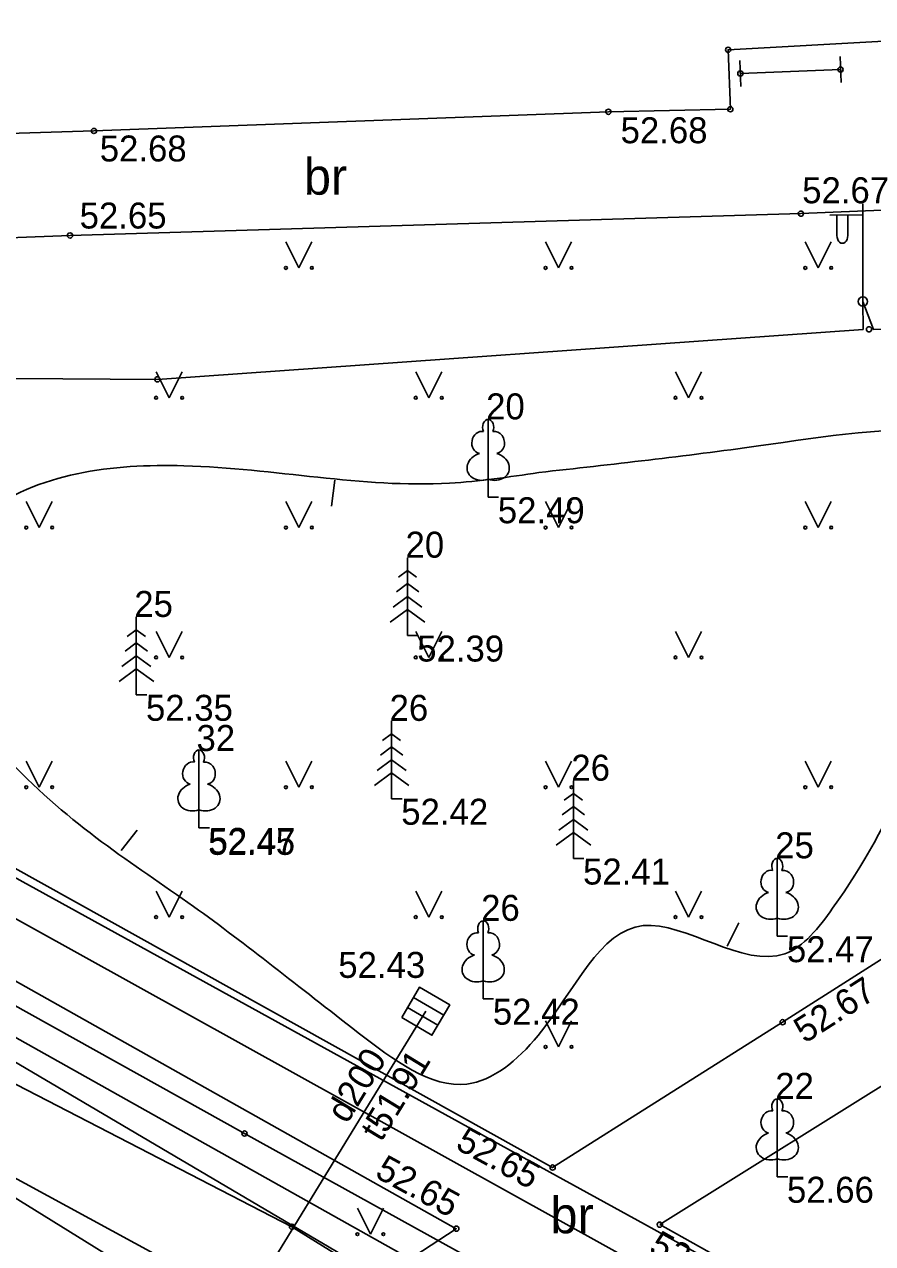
# Model space of a CAD drawing. Extents: x 619806 to 620082, y 405176 to 405386.
# Drawn here: x 619852.21 to 619868.55, y 405268.71 to 405292.19 of the extents above; entities that cross this region are included whole.
import ezdxf

# ---------------------------------------------------------------- set-up
doc = ezdxf.new("R2010")
doc.units = 0
for name, color, linetype in [('24', 7, 'Continuous'), ('APGR_SARK_####_####_#', 7, 'Continuous'), ('APGS_ELEM_####_####_#', 7, 'Continuous'), ('APGS_VADP_ZSPR_####_#', 7, 'Continuous'), ('BUVE_SOLS_####_####_#', 7, 'Continuous'), ('CELI_CMAL_####_####_#', 7, 'Continuous'), ('CELI_CSEG_####_TKST_#', 7, 'Continuous'), ('ELEK_VADP_ZSPR_####_#', 7, 'Continuous'), ('LKAN_ELEM_####_####_#', 7, 'Continuous'), ('LKAN_ELEM_PAST_TKST_#', 7, 'Continuous'), ('LKAN_VADP_PAST_####_#', 7, 'Continuous'), ('LKAN_VADP_PAST_TKST_#', 7, 'Continuous'), ('RAMI_UZMR_####_####_#', 7, 'Continuous'), ('RELJ_AATZ_####_TKST_#', 7, 'Continuous'), ('RELJ_ELEM_####_####_#', 7, 'Continuous'), ('RELJ_HORZ_PAMT_####_#', 7, 'Continuous'), ('ROBZ_UZMR_####_####_#', 7, 'Continuous'), ('SAKK_KKAN_####_####_#', 7, 'Continuous'), ('SAKT_VADP_KABE_####_#', 7, 'Continuous'), ('TERT_DIAM_####_TKST_#', 7, 'Continuous'), ('TERT_ELEM_####_####_#', 7, 'Continuous')]:
    doc.layers.add(name, color=color, linetype=linetype)

msp = doc.modelspace()

# ---------------------------------------------------------------- linework, layer by layer
at = {"layer": '24'}
msp.add_line((619862.459, 405270.018), (619864.152, 405269.086), dxfattribs=at)
at = {"layer": 'APGR_SARK_####_####_#'}
msp.add_lwpolyline([(619990.053, 405197.403), (619966.019, 405209.806), (619941.986, 405222.21), (619880.273, 405256.839), (619818.56, 405291.467)], dxfattribs=at)
at = {"layer": 'APGS_ELEM_####_####_#'}
for p, q in [((619868.359, 405286.853), (619868.359, 405288.736)), ((619868.359, 405288.52), (619867.724, 405288.515)), ((619867.859, 405288.516), (619867.859, 405288.124)), ((619868.069, 405288.518), (619868.069, 405288.124))]:
    msp.add_line(p, q, dxfattribs=at)
msp.add_circle((619868.359, 405286.853), 0.09, dxfattribs=at)
msp.add_ellipse((619867.964, 405288.124), major_axis=(0, 0.151), ratio=0.695971, start_param=1.570796, end_param=4.712389, dxfattribs=at)
at = {"layer": 'APGS_VADP_ZSPR_####_#'}
for points in [[(619889.151, 405287.633), (619888.839, 405287.188), (619868.564, 405286.313), (619868.359, 405286.853), (619868.361, 405286.315), (619854.776, 405285.354), (619845.67, 405285.418), (619844.273, 405285.984), (619845.432, 405287.623), (619843.395, 405290.297), (619835.199, 405289.5), (619828.336, 405290.779), (619827.279, 405290.766)], [(619827.279, 405290.766), (619828.233, 405290.484), (619831.689, 405284.666), (619835.137, 405280.637), (619844.802, 405275.519), (619857.367, 405269.037), (619864.044, 405264.897), (619871.373, 405258.791), (619881.17, 405253.384), (619884.232, 405252.778), (619898.622, 405244.594), (619910.805, 405239.254), (619917.273, 405236.249), (619923.426, 405231.863), (619936.8, 405224.512), (619938.618, 405223.547), (619972.929, 405204.127)]]:
    msp.add_lwpolyline(points, dxfattribs=at)
at = {"layer": 'BUVE_SOLS_####_####_#'}
for p, q in [((619867.938, 405291.069), (619867.918, 405291.569)), ((619866.009, 405290.993), (619865.989, 405291.493)), ((619865.999, 405291.243), (619867.928, 405291.319))]:
    msp.add_line(p, q, dxfattribs=at)
at = {"layer": 'CELI_CMAL_####_####_#'}
for points in [[(619901.141, 405301.297), (619895.285, 405291.495), (619886.767, 405291.266), (619876.357, 405290.867), (619868.929, 405290.713), (619868.879, 405291.869), (619865.764, 405291.699), (619865.807, 405290.556), (619863.458, 405290.505), (619853.554, 405290.137), (619841.43, 405289.76), (619840.169, 405289.507), (619836.17, 405288.32), (619833.502, 405287.788), (619826.905, 405297.999), (619827.372, 405299.068), (619837.906, 405304.107), (619846.534, 405308.229), (619856.914, 405313.201), (619868.255, 405318.592), (619880.738, 405324.67), (619889.516, 405328.858), (619904.867, 405336.211)], [(619859.084, 405268.056), (619860.53, 405268.999), (619849.818, 405275.016), (619839.176, 405280.957), (619830.556, 405285.755), (619828.304, 405287.001), (619823.674, 405289.625), (619822.58, 405290.149), (619821.807, 405290.092)], [(619836.706, 405284.543), (619837.518, 405286.469), (619840.363, 405287.459), (619841.354, 405287.676), (619853.093, 405288.124), (619867.164, 405288.545), (619875.272, 405288.879), (619893.318, 405289.417), (619886.606, 405285.41), (619875.838, 405278.602), (619871.198, 405275.77), (619866.813, 405272.975), (619862.385, 405270.176), (619850.722, 405276.664), (619841.154, 405281.99), (619836.706, 405284.543)], [(619864.449, 405269.077), (619869.423, 405272.184), (619872.398, 405274.064), (619878.606, 405278.004), (619888.543, 405284.278), (619893.459, 405287.265), (619890.801, 405281.299), (619887.26, 405273.308), (619884.168, 405266.346), (619883.371, 405264.557), (619881.435, 405260.185), (619881.348, 405260.055), (619881.222, 405259.974), (619881.004, 405259.965), (619880.8, 405260.037), (619870.43, 405265.727), (619864.449, 405269.077)]]:
    msp.add_lwpolyline(points, dxfattribs=at)
at = {"layer": 'ELEK_VADP_ZSPR_####_#'}
for points in [[(619827.133, 405291.802), (619827.743, 405291.898), (619828.762, 405290.038), (619831.425, 405286.162), (619834.68, 405283.716), (619844.517, 405277.484), (619856.454, 405270.832), (619868.451, 405264.196), (619879.269, 405258.357), (619888.402, 405252.405), (619901.725, 405245.908), (619900.354, 405242.567), (619899.734, 405241.465)], [(619827.133, 405291.802), (619827.704, 405291.789), (619828.409, 405290.12), (619829.758, 405288.499), (619829.214, 405285.683), (619831.9, 405284.021), (619834.586, 405281.015), (619842.057, 405276.848), (619851.121, 405270.16), (619862.697, 405262.983), (619874.919, 405256.089), (619882.875, 405253.63), (619881.737, 405251.572)]]:
    msp.add_lwpolyline(points, dxfattribs=at)
at = {"layer": 'LKAN_ELEM_####_####_#'}
for p, q in [((619859.707, 405273.454), (619860.289, 405273.112)), ((619859.593, 405273.26), (619860.175, 405272.918))]:
    msp.add_line(p, q, dxfattribs=at)
msp.add_lwpolyline([(619859.479, 405273.066), (619859.821, 405273.648), (619860.403, 405273.307), (619860.061, 405272.724)], close=True, dxfattribs=at)
at = {"layer": 'LKAN_VADP_PAST_####_#'}
msp.add_lwpolyline([(619859.941, 405273.186), (619855.352, 405265.688)], dxfattribs=at)
at = {"layer": 'RAMI_UZMR_####_####_#'}
msp.add_lwpolyline([(619874.687, 405324.979), (619926.719, 405349.544), (619966.669, 405369.042), (620021.738, 405292.03), (620049.703, 405275.476), (620026.189, 405242.287), (620012.147, 405222.917), (619996.603, 405200.928), (619989.997, 405199.173), (619982.328, 405199.155), (619922.669, 405233.014), (619882.137, 405255.756), (619859.084, 405268.056), (619820.646, 405290.715), (619813.744, 405295.206), (619820.645, 405298.752)], close=True, dxfattribs=at)
at = {"layer": 'RELJ_ELEM_####_####_#'}
for centre in [(619865.764, 405291.699), (619865.999, 405291.243), (619867.928, 405291.319), (619865.807, 405290.556), (619863.458, 405290.505), (619853.554, 405290.137), (619867.164, 405288.545), (619853.093, 405288.124), (619868.477, 405286.317), (619854.776, 405285.354), (619866.813, 405272.975), (619856.454, 405270.832), (619862.385, 405270.176), (619857.367, 405269.037), (619860.53, 405268.999), (619864.449, 405269.077)]:
    msp.add_circle(centre, 0.05, dxfattribs=at)
at = {"layer": 'RELJ_HORZ_PAMT_####_#'}
for p, q in [((619858.129, 405282.915), (619858.189, 405283.411)), ((619854.388, 405276.676), (619854.08, 405276.282)), ((619865.972, 405274.886), (619865.746, 405274.44))]:
    msp.add_line(p, q, dxfattribs=at)
msp.add_spline([(619862.12, 405283.56), (619866.347, 405284.072), (619870.176, 405284.36), (619872.57, 405283.726), (619875.877, 405282.305), (619878.056, 405282.964), (619882.355, 405286.311), (619884.573, 405287.696), (619885.242, 405286.98), (619884.066, 405285.895), (619878.235, 405281.695), (619876.552, 405280.844), (619873.556, 405282.133), (619871.504, 405282.549), (619870.25, 405280.5), (619867.776, 405275.169), (619866.854, 405274.292), (619864.131, 405274.836), (619862.108, 405272.722), (619860.734, 405271.784), (619858.644, 405272.772), (619855.468, 405275.204), (619851.943, 405277.991), (619850.454, 405281.625), (619851.371, 405282.722), (619855.287, 405283.69), (619860.401, 405283.354), (619862.12, 405283.56)], degree=3, dxfattribs=at)
at = {"layer": 'ROBZ_UZMR_####_####_#'}
for p, q in [((619862.459, 405270.018), (619818.193, 405294.391)), ((619881.818, 405259.359), (619864.152, 405269.086))]:
    msp.add_line(p, q, dxfattribs=at)
at = {"layer": 'SAKK_KKAN_####_####_#'}
msp.add_lwpolyline([(619816.151, 405294.73), (619816.825, 405294), (619832.922, 405285.576), (619895.115, 405251.073), (619918.714, 405238.138)], dxfattribs=at)
at = {"layer": 'SAKT_VADP_KABE_####_#'}
msp.add_lwpolyline([(619817.668, 405301.762), (619818.308, 405291.251), (619820.058, 405288.244), (619821.78, 405286.435), (619865.996, 405262.382), (619894.538, 405246.913), (619928.954, 405228.717), (619988.18, 405195.595)], dxfattribs=at)
at = {"layer": 'TERT_ELEM_####_####_#'}
for p, q in [((619857.25, 405288), (619857.5, 405287.5)), ((619857.5, 405287.5), (619857.75, 405288)), ((619862.25, 405288), (619862.5, 405287.5)), ((619862.5, 405287.5), (619862.75, 405288)), ((619867.25, 405288), (619867.5, 405287.5)), ((619867.5, 405287.5), (619867.75, 405288)), ((619854.75, 405285.5), (619855, 405285)), ((619855, 405285), (619855.25, 405285.5)), ((619859.75, 405285.5), (619860, 405285)), ((619860, 405285), (619860.25, 405285.5)), ((619864.75, 405285.5), (619865, 405285)), ((619865, 405285), (619865.25, 405285.5)), ((619861.144, 405283.43), (619861.144, 405283.083)), ((619861.144, 405283.083), (619861.344, 405283.083)), ((619852.25, 405283), (619852.5, 405282.5)), ((619852.5, 405282.5), (619852.75, 405283)), ((619857.25, 405283), (619857.5, 405282.5)), ((619857.5, 405282.5), (619857.75, 405283)), ((619862.25, 405283), (619862.5, 405282.5)), ((619862.5, 405282.5), (619862.75, 405283)), ((619867.25, 405283), (619867.5, 405282.5)), ((619867.5, 405282.5), (619867.75, 405283)), ((619859.592, 405281.92), (619859.592, 405280.42)), ((619859.592, 405281.67), (619859.416, 405281.542)), ((619859.592, 405281.67), (619859.766, 405281.542)), ((619859.592, 405281.42), (619859.376, 405281.262)), ((619859.592, 405281.42), (619859.808, 405281.262)), ((619859.592, 405281.17), (619859.314, 405280.966)), ((619859.592, 405281.17), (619859.87, 405280.966)), ((619854.37, 405280.779), (619854.37, 405279.279)), ((619859.592, 405280.92), (619859.26, 405280.676)), ((619859.592, 405280.92), (619859.926, 405280.676)), ((619854.37, 405280.529), (619854.194, 405280.401)), ((619854.37, 405280.529), (619854.544, 405280.401)), ((619854.75, 405280.5), (619855, 405280)), ((619855, 405280), (619855.25, 405280.5)), ((619859.75, 405280.5), (619860, 405280)), ((619860, 405280), (619860.25, 405280.5)), ((619864.75, 405280.5), (619865, 405280)), ((619865, 405280), (619865.25, 405280.5)), ((619854.37, 405280.279), (619854.154, 405280.121)), ((619854.37, 405280.279), (619854.586, 405280.121)), ((619859.592, 405280.42), (619859.792, 405280.42)), ((619854.37, 405280.029), (619854.092, 405279.825)), ((619854.37, 405280.029), (619854.648, 405279.825)), ((619854.37, 405279.779), (619854.038, 405279.535)), ((619854.37, 405279.779), (619854.704, 405279.535)), ((619854.37, 405279.279), (619854.57, 405279.279)), ((619859.285, 405278.778), (619859.285, 405277.278)), ((619859.285, 405278.528), (619859.109, 405278.4)), ((619859.285, 405278.528), (619859.459, 405278.4)), ((619859.285, 405278.278), (619859.069, 405278.12)), ((619859.285, 405278.278), (619859.501, 405278.12)), ((619852.25, 405278), (619852.5, 405277.5)), ((619852.5, 405277.5), (619852.75, 405278)), ((619857.25, 405278), (619857.5, 405277.5)), ((619857.5, 405277.5), (619857.75, 405278)), ((619859.285, 405278.028), (619859.007, 405277.824)), ((619859.285, 405278.028), (619859.563, 405277.824)), ((619862.25, 405278), (619862.5, 405277.5)), ((619862.5, 405277.5), (619862.75, 405278)), ((619867.25, 405278), (619867.5, 405277.5)), ((619867.5, 405277.5), (619867.75, 405278)), ((619859.285, 405277.778), (619858.953, 405277.534)), ((619859.285, 405277.778), (619859.619, 405277.534)), ((619862.785, 405277.626), (619862.785, 405276.126)), ((619859.285, 405277.278), (619859.485, 405277.278)), ((619862.785, 405277.376), (619862.609, 405277.248)), ((619862.785, 405277.376), (619862.959, 405277.248)), ((619855.576, 405277.064), (619855.576, 405276.717)), ((619862.785, 405277.126), (619862.569, 405276.968)), ((619862.785, 405277.126), (619863.001, 405276.968)), ((619862.785, 405276.876), (619862.507, 405276.672)), ((619862.785, 405276.876), (619863.063, 405276.672)), ((619855.576, 405276.717), (619855.776, 405276.717)), ((619862.785, 405276.626), (619862.453, 405276.382)), ((619862.785, 405276.626), (619863.119, 405276.382)), ((619862.785, 405276.126), (619862.985, 405276.126)), ((619854.75, 405275.5), (619855, 405275)), ((619855, 405275), (619855.25, 405275.5)), ((619859.75, 405275.5), (619860, 405275)), ((619860, 405275), (619860.25, 405275.5)), ((619864.75, 405275.5), (619865, 405275)), ((619865, 405275), (619865.25, 405275.5)), ((619866.71, 405274.978), (619866.71, 405274.631)), ((619866.71, 405274.631), (619866.91, 405274.631)), ((619861.048, 405273.774), (619861.048, 405273.427)), ((619861.048, 405273.427), (619861.248, 405273.427)), ((619862.25, 405273), (619862.5, 405272.5)), ((619862.5, 405272.5), (619862.75, 405273)), ((619866.711, 405270.346), (619866.711, 405269.999)), ((619866.711, 405269.999), (619866.911, 405269.999)), ((619858.627, 405269.395), (619858.877, 405268.895)), ((619858.877, 405268.895), (619859.127, 405269.395))]:
    msp.add_line(p, q, dxfattribs=at)
for points in [[(619861.144, 405284.583), (619861.144, 405283.43)], [(619861.234, 405284.351), (619861.233, 405284.352)], [(619855.576, 405278.217), (619855.576, 405277.064)], [(619855.666, 405277.985), (619855.665, 405277.986)], [(619866.71, 405276.131), (619866.71, 405274.978)], [(619866.8, 405275.899), (619866.799, 405275.9)], [(619861.048, 405274.927), (619861.048, 405273.774)], [(619861.138, 405274.695), (619861.137, 405274.696)], [(619866.711, 405271.499), (619866.711, 405270.346)], [(619866.801, 405271.267), (619866.8, 405271.268)]]:
    msp.add_lwpolyline(points, dxfattribs=at)
for centre, radius in [((619857.25, 405287.5), 0.028), ((619857.75, 405287.5), 0.0263), ((619862.25, 405287.5), 0.028), ((619862.75, 405287.5), 0.0263), ((619867.25, 405287.5), 0.028), ((619867.75, 405287.5), 0.0263), ((619854.75, 405285), 0.028), ((619855.25, 405285), 0.0263), ((619859.75, 405285), 0.028), ((619860.25, 405285), 0.0263), ((619864.75, 405285), 0.028), ((619865.25, 405285), 0.0263), ((619852.25, 405282.5), 0.028), ((619852.75, 405282.5), 0.0263), ((619857.25, 405282.5), 0.028), ((619857.75, 405282.5), 0.0263), ((619862.25, 405282.5), 0.028), ((619862.75, 405282.5), 0.0263), ((619867.25, 405282.5), 0.028), ((619867.75, 405282.5), 0.0263), ((619854.75, 405280), 0.028), ((619855.25, 405280), 0.0263), ((619859.75, 405280), 0.028), ((619860.25, 405280), 0.0263), ((619864.75, 405280), 0.028), ((619865.25, 405280), 0.0263), ((619852.25, 405277.5), 0.028), ((619852.75, 405277.5), 0.0263), ((619857.25, 405277.5), 0.028), ((619857.75, 405277.5), 0.0263), ((619862.25, 405277.5), 0.028), ((619862.75, 405277.5), 0.0263), ((619867.25, 405277.5), 0.028), ((619867.75, 405277.5), 0.0263), ((619854.75, 405275), 0.028), ((619855.25, 405275), 0.0263), ((619859.75, 405275), 0.028), ((619860.25, 405275), 0.0263), ((619864.75, 405275), 0.028), ((619865.25, 405275), 0.0263), ((619862.25, 405272.5), 0.028), ((619862.75, 405272.5), 0.0263), ((619858.626, 405268.894), 0.028), ((619859.126, 405268.894), 0.0263)]:
    msp.add_circle(centre, radius, dxfattribs=at)
for centre, major_axis, ratio, start_param, end_param in [((619861.144, 405284.433), (0, -0.15), 0.707107, 3.14537, 5.287485), ((619861.144, 405284.433), (0, -0.15), 0.707107, 0.995701, 3.137816), ((619861.016, 405284.138), (-0.039, -0.212), 0.861323, 3.141593, 6.283185), ((619861.272, 405284.138), (0.039, -0.212), 0.861323, 0, 3.141593), ((619861.054, 405283.676), (0.307, 0.095), 0.814445, 1.570796, 4.752015), ((619861.234, 405283.676), (-0.307, 0.095), 0.814445, 1.531171, 4.712389), ((619855.576, 405278.067), (0, -0.15), 0.707107, 3.14537, 5.287485), ((619855.576, 405278.067), (0, -0.15), 0.707107, 0.995701, 3.137816), ((619855.448, 405277.772), (-0.039, -0.212), 0.861323, 3.141593, 6.283185), ((619855.704, 405277.772), (0.039, -0.212), 0.861323, 0, 3.141593), ((619855.486, 405277.31), (0.307, 0.095), 0.814445, 1.570796, 4.752015), ((619855.666, 405277.31), (-0.307, 0.095), 0.814445, 1.531171, 4.712389), ((619866.71, 405275.981), (0, -0.15), 0.707107, 3.14537, 5.287485), ((619866.71, 405275.981), (0, -0.15), 0.707107, 0.995701, 3.137816), ((619866.582, 405275.686), (-0.039, -0.212), 0.861323, 3.141593, 6.283185), ((619866.838, 405275.686), (0.039, -0.212), 0.861323, 0, 3.141593), ((619866.62, 405275.224), (0.307, 0.095), 0.814445, 1.570796, 4.752015), ((619866.8, 405275.224), (-0.307, 0.095), 0.814445, 1.531171, 4.712389), ((619861.048, 405274.777), (0, -0.15), 0.707107, 3.14537, 5.287485), ((619861.048, 405274.777), (0, -0.15), 0.707107, 0.995701, 3.137816), ((619860.92, 405274.482), (-0.039, -0.212), 0.861323, 3.141593, 6.283185), ((619861.176, 405274.482), (0.039, -0.212), 0.861323, 0, 3.141593), ((619860.958, 405274.02), (0.307, 0.095), 0.814445, 1.570796, 4.752015), ((619861.138, 405274.02), (-0.307, 0.095), 0.814445, 1.531171, 4.712389), ((619866.711, 405271.349), (0, -0.15), 0.707107, 3.14537, 5.287485), ((619866.711, 405271.349), (0, -0.15), 0.707107, 0.995701, 3.137816), ((619866.583, 405271.054), (-0.039, -0.212), 0.861323, 3.141593, 6.283185), ((619866.839, 405271.054), (0.039, -0.212), 0.861323, 0, 3.141593), ((619866.621, 405270.592), (0.307, 0.095), 0.814445, 1.570796, 4.752015), ((619866.801, 405270.592), (-0.307, 0.095), 0.814445, 1.531171, 4.712389)]:
    msp.add_ellipse(centre, major_axis=major_axis, ratio=ratio, start_param=start_param, end_param=end_param, dxfattribs=at)

# ---------------------------------------------------------------- texts
at = {"layer": 'CELI_CSEG_####_TKST_#'}
for p in [(619857.597, 405288.91), (619862.344, 405268.911)]:
    msp.add_text('br', height=0.7, dxfattribs=at).set_placement(p)
at = {"layer": 'LKAN_ELEM_PAST_TKST_#'}
msp.add_text(' 52.43', height=0.5, dxfattribs=at).set_placement((619858.073, 405273.829))
at = {"layer": 'LKAN_VADP_PAST_TKST_#'}
for s, p in [('d200', (619858.428, 405271.002)), ('t51.91', (619859.083, 405270.653))]:
    msp.add_text(s, height=0.5, rotation=58.5322, dxfattribs=at).set_placement(p)
at = {"layer": 'RELJ_AATZ_####_TKST_#'}
for s, p in [(' 52.68', (619863.508, 405289.9)), (' 52.68', (619853.48, 405289.549)), (' 52.67', (619867.004, 405288.744)), (' 52.65', (619853.093, 405288.258)), (' 52.49', (619861.144, 405282.583)), (' 52.39', (619859.592, 405279.92)), (' 52.35', (619854.37, 405278.779)), (' 52.42', (619859.285, 405276.778)), (' 52.47', (619855.576, 405276.217)), (' 52.45', (619855.567, 405276.198)), (' 52.41', (619862.785, 405275.626)), (' 52.47', (619866.71, 405274.131)), (' 52.42', (619861.048, 405272.927)), (' 52.66', (619866.711, 405269.499))]:
    msp.add_text(s, height=0.5, dxfattribs=at).set_placement(p)
for s, rotation, p in [(' 52.67', 32.5134, (619867.082, 405272.456)), (' 52.65', 331.2412, (619860.328, 405270.641)), (' 52.65', 331.3759, (619858.778, 405270.093)), (' 52.65', 330.7465, (619864.049, 405268.641))]:
    msp.add_text(s, height=0.5, rotation=rotation, dxfattribs=at).set_placement(p)
at = {"layer": 'TERT_DIAM_####_TKST_#'}
for s, p in [(' 20', (619860.919, 405284.583)), (' 20', (619859.367, 405281.92)), (' 25', (619854.145, 405280.779)), (' 26', (619859.06, 405278.778)), (' 32', (619855.342, 405278.198)), (' 26', (619862.56, 405277.626)), (' 25', (619866.485, 405276.131)), (' 26', (619860.823, 405274.927)), (' 22', (619866.486, 405271.499))]:
    msp.add_text(s, height=0.5, dxfattribs=at).set_placement(p)

doc.saveas('drawing.dxf')
